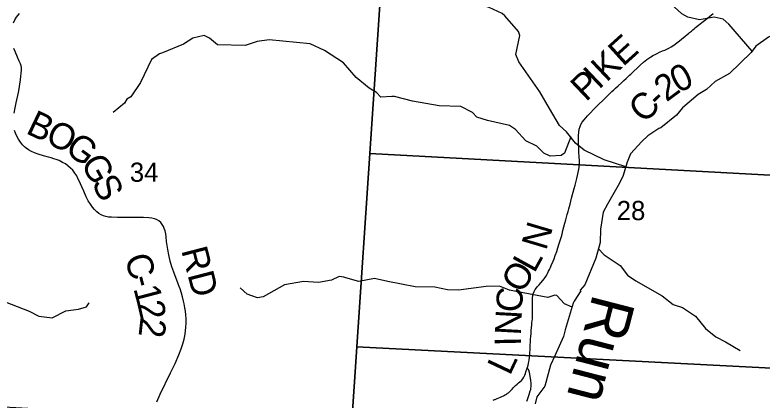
# Model space of a CAD drawing. Extents: x 396.2 to 468.4, y 232.6 to 279.1.
# Drawn here: x 415.736 to 417.363, y 273.571 to 274.409 of the extents above; entities that cross this region are included whole.
import ezdxf

# ---------------------------------------------------------------- set-up
doc = ezdxf.new("R2010")
doc.units = 0
for name, color, linetype in [('GM_X_County_Road', 7, 'Continuous'), ('GM_X_County_Road_Text', 7, 'Continuous'), ('GM_X_Minor_River', 7, 'Continuous'), ('GM_X_Minor_River_Text', 7, 'Continuous'), ('GM_X_Section', 7, 'Continuous'), ('GM_X_Section_Text', 7, 'Continuous')]:
    doc.layers.add(name, color=color, linetype=linetype)

msp = doc.modelspace()

# ---------------------------------------------------------------- linework, layer by layer
at = {"layer": 'GM_X_County_Road'}
for points in [[(415.7323, 274.3919), (415.7356, 274.3984), (415.7393, 274.404), (415.7453, 274.4118)], [(416.8518, 273.641), (416.852, 273.6418), (416.8534, 273.6465), (416.8544, 273.6502), (416.8552, 273.6544), (416.8558, 273.6576), (416.8565, 273.664), (416.8571, 273.6688), (416.8574, 273.6745), (416.8578, 273.6801), (416.858, 273.6843), (416.8584, 273.6906), (416.8587, 273.6966), (416.8591, 273.7026), (416.8595, 273.7096), (416.8599, 273.7151), (416.8606, 273.7224), (416.8611, 273.7289), (416.8616, 273.7335), (416.862, 273.739), (416.8624, 273.7433), (416.8628, 273.7476), (416.863, 273.7543), (416.8633, 273.7609), (416.8632, 273.7695), (416.8631, 273.7757), (416.863, 273.7793), (416.8629, 273.783), (416.8628, 273.7848), (416.8628, 273.7866), (416.8629, 273.7884), (416.863, 273.7908), (416.8632, 273.7932), (416.8639, 273.7984), (416.8647, 273.8018), (416.8666, 273.807), (416.8689, 273.8112), (416.8717, 273.8152), (416.8742, 273.8179), (416.8776, 273.8218), (416.8813, 273.8258), (416.8853, 273.8307), (416.8883, 273.8344), (416.8906, 273.8375), (416.8934, 273.8421), (416.896, 273.8464), (416.8983, 273.8511), (416.9002, 273.8547), (416.9021, 273.8592), (416.9041, 273.8637), (416.9081, 273.8731), (416.9101, 273.8784), (416.9128, 273.8853), (416.9158, 273.8942), (416.9186, 273.9024), (416.9216, 273.9118), (416.9237, 273.9183), (416.926, 273.9266), (416.9275, 273.9321), (416.9295, 273.9399), (416.9315, 273.9476), (416.9336, 273.9556), (416.9356, 273.9629), (416.9371, 273.9687), (416.9388, 273.9749), (416.9405, 273.9808), (416.9421, 273.9867), (416.9449, 273.9969), (416.9483, 274.0099), (416.954, 274.031), (416.956, 274.0384), (416.9574, 274.0441), (416.9597, 274.0529), (416.9614, 274.0593), (416.9627, 274.0659), (416.9642, 274.0731), (416.9646, 274.0769), (416.965, 274.0806), (416.9656, 274.0864), (416.9655, 274.0911), (416.9655, 274.0936), (416.9651, 274.0989), (416.9644, 274.1114), (416.9632, 274.1356), (416.9633, 274.1466), (416.9639, 274.1539), (416.965, 274.1605), (416.9667, 274.1663), (416.9688, 274.1707), (416.9716, 274.1754), (416.9757, 274.1808), (416.983, 274.1892), (416.9885, 274.1951), (416.9966, 274.2036), (417.0021, 274.2089), (417.0085, 274.2152), (417.0157, 274.2222), (417.0202, 274.2266), (417.0241, 274.2305), (417.0301, 274.2363), (417.0362, 274.2422), (417.0402, 274.246), (417.044, 274.2495), (417.0498, 274.2548), (417.0567, 274.261), (417.0623, 274.2661), (417.0673, 274.2707), (417.0745, 274.2776), (417.0772, 274.2801), (417.0979, 274.2998), (417.1048, 274.306), (417.1125, 274.3122), (417.1206, 274.3178), (417.1271, 274.3214), (417.1303, 274.3231), (417.1345, 274.3251), (417.1398, 274.3277), (417.1462, 274.3305), (417.1511, 274.3326), (417.1556, 274.3346), (417.16, 274.3369), (417.1652, 274.3396), (417.1708, 274.3431), (417.1776, 274.3481), (417.1832, 274.3526), (417.1879, 274.3561), (417.1921, 274.3596), (417.1953, 274.3623), (417.2003, 274.3664), (417.2027, 274.3684), (417.2051, 274.3704), (417.2072, 274.3721), (417.2093, 274.3739), (417.2122, 274.3763), (417.2154, 274.3789), (417.2183, 274.3814), (417.225, 274.3869), (417.232, 274.3924), (417.2407, 274.3992), (417.2486, 274.4055), (417.2571, 274.4124)], [(415.7338, 274.1954), (415.7361, 274.2069), (415.7383, 274.2179), (415.7431, 274.2404), (415.7447, 274.2483), (415.7461, 274.2585), (415.7473, 274.268), (415.7483, 274.2754), (415.7491, 274.2815), (415.7497, 274.2896), (415.7495, 274.2946), (415.7488, 274.2983), (415.7475, 274.3025), (415.7451, 274.3083), (415.7413, 274.3168), (415.7357, 274.3293), (415.7329, 274.3361)], [(416.0449, 273.567), (416.0523, 273.5834), (416.0748, 273.6298), (416.0845, 273.6506), (416.0928, 273.6693), (416.0979, 273.682), (416.1016, 273.6933), (416.1041, 273.7029), (416.1063, 273.7145), (416.1081, 273.7293), (416.1087, 273.738), (416.1087, 273.7474), (416.108, 273.7561), (416.1068, 273.7644), (416.1057, 273.7715), (416.104, 273.78), (416.1028, 273.7861), (416.1004, 273.7956), (416.0983, 273.8036), (416.0954, 273.8131), (416.0936, 273.8179), (416.0915, 273.8236), (416.0815, 273.849), (416.0774, 273.8607), (416.0739, 273.8732), (416.0708, 273.8865), (416.0686, 273.8981), (416.0673, 273.9074), (416.0661, 273.9159), (416.0649, 273.9257), (416.064, 273.9326), (416.0626, 273.9393), (416.061, 273.9441), (416.059, 273.9487), (416.0564, 273.953), (416.0532, 273.957), (416.0489, 273.9607), (416.044, 273.9635), (416.0393, 273.9653), (416.0338, 273.9666), (416.0275, 273.9674), (416.0157, 273.9679), (416.0033, 273.968), (415.9935, 273.9681), (415.9841, 273.9681), (415.9714, 273.9682), (415.9593, 273.9683), (415.9456, 273.9685), (415.9395, 273.9689), (415.9334, 273.9699), (415.9282, 273.9716), (415.9232, 273.9739), (415.9185, 273.9769), (415.9137, 273.9807), (415.909, 273.9855), (415.9047, 273.9908), (415.9003, 273.9968), (415.8953, 274.0046), (415.8909, 274.0128), (415.8854, 274.0252), (415.8812, 274.0349), (415.8783, 274.0415), (415.8752, 274.0482), (415.8727, 274.0533), (415.8701, 274.0585), (415.8661, 274.0649), (415.8615, 274.0708), (415.8567, 274.0758), (415.8511, 274.0807), (415.8455, 274.0847), (415.8395, 274.0881), (415.8316, 274.0918), (415.8256, 274.094), (415.8205, 274.096), (415.8144, 274.0979), (415.8086, 274.0997), (415.798, 274.1026), (415.7865, 274.1058), (415.7784, 274.1086), (415.7716, 274.1117), (415.7652, 274.1153), (415.7601, 274.1188), (415.7564, 274.122), (415.7522, 274.1265), (415.7475, 274.1323), (415.743, 274.1389), (415.7394, 274.1453), (415.7367, 274.1516), (415.7348, 274.1574)], [(416.7775, 273.5703), (416.7803, 273.5716), (416.782, 273.5723), (416.7865, 273.5742), (416.7895, 273.5755), (416.7934, 273.5771), (416.7963, 273.5785), (416.7996, 273.5799), (416.8018, 273.5812), (416.8049, 273.5829), (416.8073, 273.5846), (416.8088, 273.5855), (416.8106, 273.5868), (416.813, 273.5888), (416.8158, 273.5913), (416.8185, 273.5945), (416.8211, 273.5974), (416.8238, 273.6001), (416.8262, 273.6026), (416.8294, 273.6054), (416.8323, 273.6079), (416.8353, 273.6105), (416.839, 273.6136), (416.842, 273.6169), (416.8444, 273.6207), (416.8465, 273.6249), (416.8476, 273.6283), (416.8489, 273.6323), (416.8509, 273.6383), (416.8518, 273.641)], [(416.851, 273.5681), (416.8521, 273.5716), (416.8556, 273.5825), (416.8584, 273.5907), (416.8593, 273.5936), (416.8598, 273.5966), (416.8602, 273.5996), (416.8603, 273.6026), (416.8603, 273.6077), (416.8598, 273.6133), (416.858, 273.623), (416.8565, 273.6307), (416.855, 273.6357), (416.8542, 273.6374), (416.8532, 273.6388), (416.8518, 273.641)]]:
    msp.add_lwpolyline(points, dxfattribs=at)
at = {"layer": 'GM_X_Minor_River'}
for points in [[(417.3417, 274.3302), (417.2912, 274.3889), (417.2783, 274.3994), (417.2589, 274.4043), (417.2267, 274.398), (417.2016, 274.4043), (417.1886, 274.4115), (417.1226, 274.4723), (417.107, 274.4821), (417.0678, 274.4986), (417.0501, 274.5334), (417.0402, 274.5447), (417.0166, 274.5587), (417.0063, 274.5662), (416.9622, 274.6389)], [(417.0665, 274.0785), (417.019, 274.0939), (416.9758, 274.1147), (416.957, 274.1301), (416.9373, 274.1546), (416.9218, 274.1684), (416.9003, 274.2052), (416.8791, 274.2415), (416.8331, 274.3068), (416.8271, 274.3225), (416.8352, 274.3641), (416.8324, 274.3729), (416.8032, 274.4069), (416.7973, 274.4124), (416.769, 274.4254), (416.7065, 274.4456), (416.7013, 274.4485), (416.6901, 274.453), (416.6596, 274.4824), (416.6299, 274.5236), (416.6084, 274.552), (416.5899, 274.5891), (416.5606, 274.6208), (416.5605, 274.6211)], [(417.4493, 274.4139), (417.4342, 274.3968), (417.4187, 274.3826), (417.3776, 274.3609), (417.35, 274.3407), (417.3394, 274.3273), (417.2926, 274.2816), (417.2608, 274.264), (417.242, 274.2469), (417.2242, 274.2358), (417.1902, 274.2069), (417.177, 274.1905), (417.1426, 274.1634), (417.1385, 274.1615), (417.1143, 274.1455), (417.1014, 274.1333), (417.0769, 274.107), (417.0697, 274.0883), (417.0603, 274.0575), (417.0501, 274.0377), (417.0264, 273.9974), (417.0169, 273.9799), (417.0113, 273.9426), (417.0109, 273.9137)], [(416.9463, 274.1434), (416.9329, 274.1084), (416.9259, 274.103), (416.9013, 274.1015), (416.8879, 274.1083), (416.8729, 274.1236), (416.8486, 274.135), (416.826, 274.1597), (416.813, 274.1684), (416.7649, 274.1791), (416.7421, 274.1863), (416.7326, 274.1965), (416.7073, 274.2094), (416.6597, 274.2113), (416.6018, 274.2211), (416.5628, 274.2311), (416.5567, 274.2313), (416.5325, 274.2298), (416.523, 274.2404), (416.507, 274.2496), (416.479, 274.2729), (416.4512, 274.3045), (416.4101, 274.3313), (416.3784, 274.346), (416.2891, 274.3545), (416.2633, 274.3512), (416.2369, 274.3425), (416.1765, 274.3441), (416.1596, 274.3587), (416.1476, 274.3644), (416.1229, 274.3587), (416.1028, 274.3453), (416.0569, 274.3266), (416.0504, 274.3246), (416.0334, 274.3118), (416.0092, 274.2617), (415.9878, 274.2305), (415.9794, 274.2258), (415.9742, 274.2169), (415.9498, 274.1968)], [(417.0109, 273.9137), (417.0008, 273.8795), (416.977, 273.8213), (416.9672, 273.8102), (416.9687, 273.8083), (416.9536, 273.7863), (416.9521, 273.7817), (416.9344, 273.7235), (416.931, 273.7094), (416.9121, 273.6668), (416.9027, 273.6466), (416.8899, 273.601), (416.8729, 273.5774), (416.8691, 273.5622)], [(417.0063, 273.9007), (417.0195, 273.8866), (417.054, 273.8638), (417.0703, 273.8424), (417.0881, 273.8301), (417.1453, 273.7979), (417.1693, 273.7789), (417.1903, 273.7725), (417.2184, 273.753), (417.2403, 273.7265), (417.2624, 273.7083), (417.2833, 273.6978), (417.3156, 273.6786)], [(416.9495, 273.7731), (416.9328, 273.78), (416.9163, 273.798), (416.9118, 273.7992), (416.8965, 273.7937), (416.8616, 273.8005), (416.8131, 273.81), (416.7914, 273.8183), (416.7619, 273.8181), (416.7016, 273.8097), (416.6778, 273.8109), (416.6507, 273.8163), (416.6073, 273.8169), (416.5483, 273.8287), (416.5187, 273.8353), (416.4848, 273.8288), (416.4567, 273.8369), (416.4522, 273.8382), (416.442, 273.8393), (416.4252, 273.8315), (416.3967, 273.8267), (416.3642, 273.8285), (416.3228, 273.8214), (416.2767, 273.7952), (416.2641, 273.7933), (416.2417, 273.8009), (416.2266, 273.815)], [(415.6709, 273.8009), (415.7669, 273.7644), (415.7874, 273.7531), (415.8164, 273.7495), (415.8467, 273.7649), (415.8737, 273.7686), (415.8912, 273.7733), (415.8975, 273.7822)]]:
    msp.add_lwpolyline(points, dxfattribs=at)
at = {"layer": 'GM_X_Section'}
for points in [[(415.5204, 274.5839), (416.5371, 274.5285), (416.5087, 274.1071), (416.4804, 273.6869), (416.4687, 273.5133), (415.4502, 273.5695), (415.4623, 273.748)], [(416.5371, 274.5285), (417.5594, 274.4718), (417.5282, 274.0521), (416.5087, 274.1071)], [(417.5282, 274.0521), (417.497, 273.6341), (416.4804, 273.6869), (416.5087, 274.1071)], [(416.4804, 273.6869), (417.497, 273.6341), (417.4832, 273.4629), (416.4687, 273.5133)]]:
    msp.add_lwpolyline(points, close=True, dxfattribs=at)

# ---------------------------------------------------------------- texts
at = {"layer": 'GM_X_County_Road_Text'}
for s, height, rotation, p in [('E', 0.0568, 42.1063, (417.0603, 274.2951)), ('K', 0.0568, 43.5342, (417.0243, 274.261)), ('I', 0.0568, 43.5731, (417.0074, 274.2449)), ('0', 0.0568, 26.9118, (417.1809, 274.2378)), ('P', 0.0568, 43.582, (416.9796, 274.2185)), ('2', 0.0568, 36.7159, (417.155, 274.2182)), ('C', 0.0568, 43.7801, (417.1058, 274.171)), ('-', 0.0568, 43.5731, (417.1395, 274.2033)), ('B', 0.0568, 334.491, (415.7571, 274.1524)), ('O', 0.0568, 333.9229, (415.7991, 274.1324)), ('G', 0.0568, 323.6099, (415.8417, 274.1118)), ('G', 0.0568, 298.751, (415.8777, 274.087)), ('S', 0.0568, 297.1229, (415.9016, 274.0436)), ('N', 0.0568, 73.4185, (416.8927, 273.8946)), ('RD', 0.05682, 284.513, (416.0975, 273.8969)), ('C', 0.0568, 288.4944, (415.9731, 273.8794)), ('L', 0.0568, 61.2064, (416.8671, 273.8452)), ('O', 0.0568, 59.2714, (416.8405, 273.8004)), ('-', 0.0568, 284.4286, (415.9875, 273.8365)), ('1', 0.0568, 284.73, (415.9933, 273.8138)), ('C', 0.0568, 86.9318, (416.8401, 273.7607)), ('2', 0.0568, 282.9386, (416.002, 273.7807)), ('N', 0.0568, 86.9277, (416.8374, 273.7107)), ('2', 0.0568, 263.6268, (416.0095, 273.7519)), ('I', 0.0568, 91.2033, (416.838, 273.6885)), ('L', 0.0568, 64.6837, (416.8138, 273.6223))]:
    msp.add_text(s, height=height, rotation=rotation, dxfattribs=at).set_placement(p)
at = {"layer": 'GM_X_Minor_River_Text'}
msp.add_text('Run', height=0.0947, rotation=255.514, dxfattribs=at).set_placement((416.9957, 273.8045))
at = {"layer": 'GM_X_Section_Text'}
for s, p in [('34', (415.9859, 274.0457)), ('28', (417.0467, 273.9623))]:
    msp.add_text(s, height=0.04186, rotation=0, dxfattribs=at).set_placement(p)

doc.saveas('drawing.dxf')
